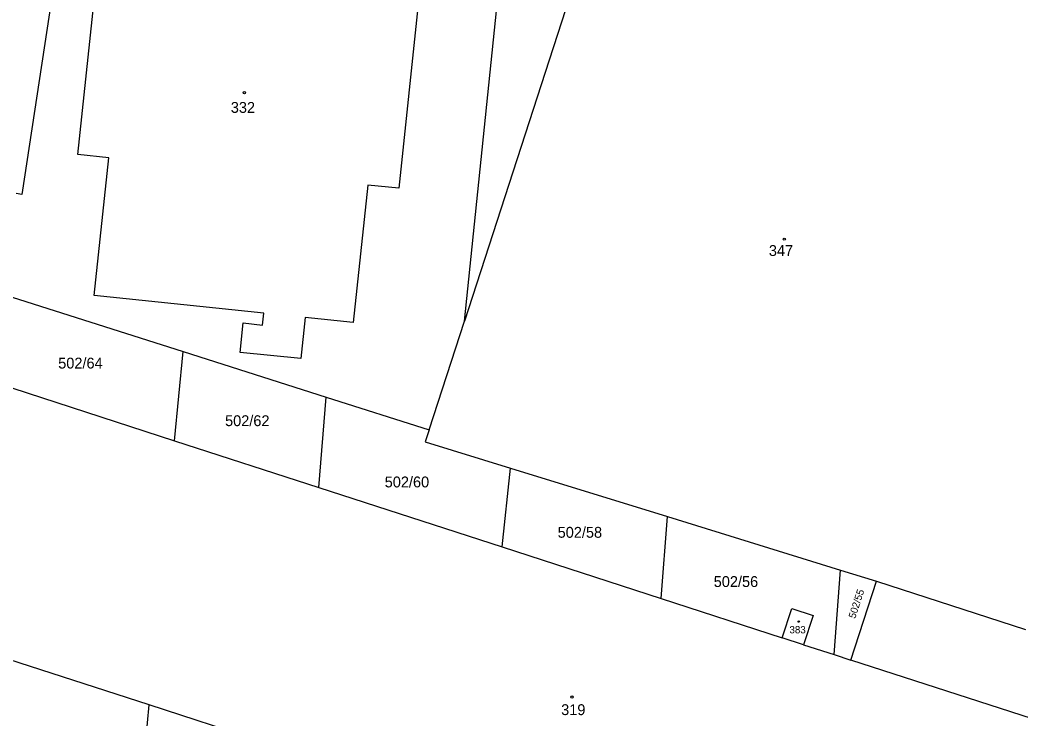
# Model space of a CAD drawing. Extents: x -701211 to -698780, y -1014269 to -1012378.
# Drawn here: x -700163.9 to -700007.4, y -1012916.2 to -1012806.8 of the extents above; entities that cross this region are included whole.
import ezdxf
from ezdxf.enums import TextEntityAlignment as Align

# ---------------------------------------------------------------- set-up
doc = ezdxf.new("R2010")
doc.units = 0
doc.header["$LTSCALE"] = 0.68
doc.layers.add('1', color=7, linetype='Continuous', lineweight=25)
doc.layers.add('5', color=7, linetype='Continuous', lineweight=25)
doc.layers.add('2', color=7, linetype='Continuous')

msp = doc.modelspace()

# ---------------------------------------------------------------- linework, layer by layer
at = {"layer": '1'}
for p, q in [((-700066.91, -1012769.42), (-700094.37, -1012854)), ((-700094.37, -1012854), (-700085.71, -1012769.77)), ((-700155.55, -1012781.25), (-700163.63, -1012834.2)), ((-700154.85, -1012827.93), (-700151.75, -1012798.62)), ((-700101.58, -1012803.88), (-700104.66, -1012833.2)), ((-700150.03, -1012828.44), (-700154.85, -1012827.93)), ((-700152.29, -1012849.99), (-700150.03, -1012828.44)), ((-700109.5, -1012832.7), (-700111.77, -1012854.25)), ((-700104.66, -1012833.2), (-700109.5, -1012832.7)), ((-700163.63, -1012834.2), (-700164.53, -1012834.04)), ((-700169.24, -1012848.95), (-700138.38, -1012858.79)), ((-700125.76, -1012852.78), (-700152.29, -1012849.99)), ((-700125.96, -1012854.62), (-700125.76, -1012852.78)), ((-700119.3, -1012853.46), (-700119.97, -1012859.87)), ((-700111.77, -1012854.25), (-700119.3, -1012853.46)), ((-700129.48, -1012858.92), (-700128.99, -1012854.3)), ((-700128.99, -1012854.3), (-700125.96, -1012854.62)), ((-700099.91, -1012871.05), (-700094.37, -1012854)), ((-700139.72, -1012872.75), (-700138.38, -1012858.79)), ((-700138.38, -1012858.79), (-700115.99, -1012865.92)), ((-700119.97, -1012859.87), (-700129.48, -1012858.92)), ((-700170.69, -1012862.7), (-700139.72, -1012872.75)), ((-700117.18, -1012880.07), (-700115.99, -1012865.92)), ((-700115.99, -1012865.92), (-700099.91, -1012871.05)), ((-700139.72, -1012872.75), (-700117.18, -1012880.07)), ((-700088.49, -1012889.38), (-700087.14, -1012877.04)), ((-700087.14, -1012877.04), (-700062.61, -1012884.62)), ((-700117.18, -1012880.07), (-700088.49, -1012889.38)), ((-700063.59, -1012897.46), (-700062.61, -1012884.62)), ((-700062.61, -1012884.62), (-700035.53, -1012892.99)), ((-700088.49, -1012889.38), (-700063.59, -1012897.46)), ((-700036.53, -1012906.24), (-700035.53, -1012892.99)), ((-700035.53, -1012892.99), (-700029.89, -1012894.73)), ((-700033.89, -1012907.1), (-700029.89, -1012894.73)), ((-700029.89, -1012894.73), (-700006.58, -1012902.29)), ((-700063.59, -1012897.46), (-700044.65, -1012903.61)), ((-700044.65, -1012903.61), (-700043.15, -1012899.01)), ((-700043.15, -1012899.01), (-700039.83, -1012900.09)), ((-700039.83, -1012900.09), (-700041.33, -1012904.69)), ((-700041.33, -1012904.69), (-700044.65, -1012903.61)), ((-700143.71, -1012914.11), (-700175.04, -1012903.95)), ((-700041.33, -1012904.69), (-700036.53, -1012906.24)), ((-700036.53, -1012906.24), (-700033.89, -1012907.1)), ((-699962.61, -1012930.17), (-700033.89, -1012907.1)), ((-700145.38, -1012931.48), (-700143.71, -1012914.11)), ((-700120.67, -1012921.58), (-700143.71, -1012914.11))]:
    msp.add_line(p, q, dxfattribs=at)
msp.add_lwpolyline([(-700099.91, -1012871.05), (-700100.51, -1012872.91), (-700087.14, -1012877.04)], dxfattribs=at)
at = {"layer": '5'}
for centre, radius in [((-700128.7968, -1012818.2492), 0.175), ((-700044.3268, -1012841.1692), 0.175), ((-700042.0546, -1012901.0594), 0.1172), ((-700077.5468, -1012912.8792), 0.175)]:
    msp.add_circle(centre, radius, dxfattribs=at)

# ---------------------------------------------------------------- texts
at = {"layer": '2'}
for s, p in [('332', (-700130.93, -1012821.395)), ('347', (-700046.74, -1012843.805)), ('319', (-700079.24, -1012915.705))]:
    msp.add_text(s, height=1.7, dxfattribs=at).set_placement(p)
for s, height, p in [('502/64', 1.7, (-700154.46, -1012861.435)), ('502/62', 1.7, (-700128.35, -1012870.455)), ('502/60', 1.7, (-700103.37, -1012880.045)), ('502/58', 1.7, (-700076.31, -1012887.935)), ('502/56', 1.7, (-700051.89, -1012895.645)), ('383', 1.14, (-700042.24, -1012902.905))]:
    msp.add_text(s, height=height, dxfattribs=at).set_placement(p, align=Align.CENTER)
msp.add_text('502/55', height=1.14, rotation=72, dxfattribs=at).set_placement((-700032.5096, -1012898.4476), align=Align.CENTER)

doc.saveas('drawing.dxf')
